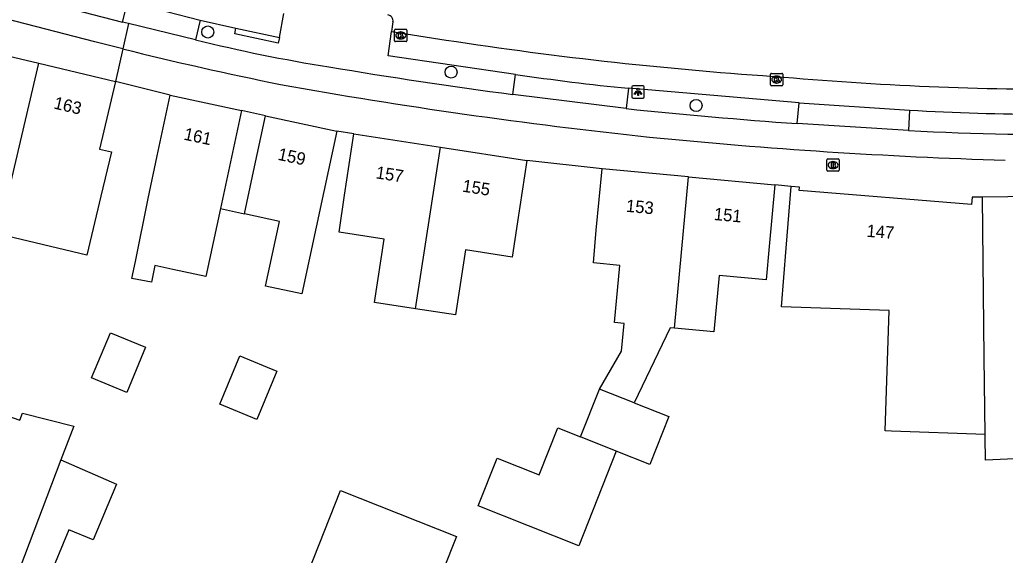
# Model space of a CAD drawing. Extents: x 158087 to 159494, y 382905 to 383981.
# Drawn here: x 158597.5 to 158677.2, y 383097.9 to 383141.2 of the extents above; entities that cross this region are included whole.
import ezdxf

# ---------------------------------------------------------------- set-up
doc = ezdxf.new("R2010")
doc.units = 0
for name, color, linetype in [('IMGEO_Boom', 7, 'Continuous'), ('IMGEO_Brandkraan', 7, 'Continuous'), ('IMGEO_Fietspad_gesloten', 7, 'Continuous'), ('IMGEO_Kolk', 7, 'Continuous'), ('IMGEO_Lichtpunt', 7, 'Continuous'), ('IMGEO_Pand', 7, 'Continuous'), ('IMGEO_Pand_nummerreeks', 7, 'Continuous'), ('IMGEO_Pand_overbouw', 7, 'Continuous'), ('IMGEO_Parkeervlak_open', 7, 'Continuous'), ('IMGEO_Rijbaan_lokaal_gesloten', 7, 'Continuous'), ('IMGEO_Voetpad_open', 7, 'Continuous')]:
    doc.layers.add(name, color=color, linetype=linetype)

msp = doc.modelspace()

# ---------------------------------------------------------------- linework, layer by layer
at = {"layer": 'IMGEO_Boom'}
for centre in [(158612.695, 383140.229), (158632.365, 383136.991), (158652.17, 383134.289)]:
    msp.add_circle(centre, 0.489, dxfattribs=at)
at = {"layer": 'IMGEO_Brandkraan'}
for p, q in [((158662.74, 383129.05), (158662.74, 383129.902)), ((158662.815, 383129.976), (158663.667, 383129.976)), ((158663.741, 383129.902), (158663.741, 383129.05)), ((158663.251, 383129.196), (158663.226, 383129.196)), ((158663.228, 383129.756), (158663.253, 383129.756)), ((158663.667, 383128.976), (158662.815, 383128.976))]:
    msp.add_line(p, q, dxfattribs=at)
for points in [[(158662.74, 383129.05), (158662.74, 383129.902)], [(158662.815, 383129.976), (158663.667, 383129.976)], [(158663.741, 383129.902), (158663.741, 383129.05)], [(158663.088, 383129.676), (158663.088, 383129.276), (158663.301, 383129.276)], [(158663.319, 383129.676), (158663.088, 383129.676)], [(158663.267, 383129.595), (158663.213, 383129.595), (158663.213, 383129.519)], [(158663.213, 383129.519), (158663.266, 383129.519)], [(158663.275, 383129.443), (158663.213, 383129.443), (158663.213, 383129.362)], [(158663.213, 383129.362), (158663.275, 383129.362)], [(158663.667, 383128.976), (158662.815, 383128.976)]]:
    msp.add_lwpolyline(points, dxfattribs=at)
for centre, radius, start, end in [((158662.817, 383129.9), 0.0765, 91.55205, 178.44795), ((158662.817, 383129.9), 0.0765, 91.55205, 178.44795), ((158663.665, 383129.9), 0.0765, 1.55205, 88.44795), ((158663.665, 383129.9), 0.0765, 1.55205, 88.44795), ((158662.817, 383129.052), 0.0765, 181.55205, 268.44795), ((158662.817, 383129.052), 0.0765, 181.55205, 268.44795), ((158663.268, 383129.557), 0.0379, 267.82845, 90.93552), ((158663.276, 383129.402), 0.0404, 269.87594, 90.50774), ((158663.307, 383129.527), 0.251, 268.66757, 293.53466), ((158663.323, 383129.531), 0.145, 59.4692, 91.53667), ((158663.348, 383129.578), 0.0922, 285.51372, 58.15012), ((158663.353, 383129.386), 0.105, 301.31148, 78.98903), ((158663.665, 383129.052), 0.0765, 271.55205, 358.44795), ((158663.665, 383129.052), 0.0765, 271.55205, 358.44795)]:
    msp.add_arc(centre, radius, start, end, dxfattribs=at)
for centre, major_axis, ratio, start_param, end_param in [((158663.227, 383129.476), (-0.387, 0.002), 0.722429, 4.712389, 7.853982), ((158663.252, 383129.476), (-0.39, 0.002), 0.717154, 1.570796, 4.712389)]:
    msp.add_ellipse(centre, major_axis=major_axis, ratio=ratio, start_param=start_param, end_param=end_param, dxfattribs=at)
at = {"layer": 'IMGEO_Fietspad_gesloten'}
for points in [[(158605.821, 383138.869), (158603.579, 383139.437), (158566.233, 383149.116), (158551.161, 383152.802)], [(158595.342, 383143.755), (158605.812, 383141.029)], [(158606.277, 383140.917), (158605.812, 383141.029)], [(158606.277, 383140.917), (158605.821, 383138.869)], [(158611.717, 383139.601), (158606.277, 383140.917)], [(158646.524, 383134.037), (158637.361, 383135.18)], [(158669.341, 383132.266), (158660.347, 383132.823)]]:
    msp.add_lwpolyline(points, dxfattribs=at)
for centre, radius, start, end in [((158641.65, 383259.404), 123.486, 255.97176, 261.07303), ((158678.323, 383430.181), 300.199, 256.02409, 258.52003), ((158692.906, 383555.601), 424.074, 260.44169, 262.4738), ((158692.742, 383549.43), 420.041, 259.83006, 263.94093), ((158692.294, 383575.88), 444.207, 264.08595, 265.87584), ((158681.389, 383358.442), 226.496, 266.95077, 275.08287), ((158689.949, 383550.143), 420.466, 264.32963, 268.25752)]:
    msp.add_arc(centre, radius, start, end, dxfattribs=at)
at = {"layer": 'IMGEO_Kolk'}
for p, q in [((158627.795, 383139.527), (158627.795, 383140.379)), ((158627.87, 383140.453), (158628.722, 383140.453)), ((158628.283, 383140.233), (158628.308, 383140.233)), ((158628.796, 383140.379), (158628.796, 383139.527)), ((158628.722, 383139.453), (158627.87, 383139.453)), ((158628.306, 383139.673), (158628.281, 383139.673)), ((158658.183, 383135.961), (158658.183, 383136.813)), ((158658.258, 383136.887), (158659.11, 383136.887)), ((158658.671, 383136.667), (158658.696, 383136.667)), ((158659.184, 383136.813), (158659.184, 383135.961)), ((158659.11, 383135.887), (158658.258, 383135.887)), ((158658.694, 383136.107), (158658.669, 383136.107))]:
    msp.add_line(p, q, dxfattribs=at)
for points in [[(158627.795, 383139.527), (158627.795, 383140.379)], [(158627.87, 383140.453), (158628.722, 383140.453)], [(158628.796, 383140.379), (158628.796, 383139.527)], [(158628.722, 383139.453), (158627.87, 383139.453)], [(158628.116, 383140.153), (158628.239, 383140.153), (158628.239, 383140.002), (158628.369, 383140.153), (158628.533, 383140.153), (158628.387, 383140.002), (158628.54, 383139.753), (158628.388, 383139.753), (158628.303, 383139.917), (158628.239, 383139.85), (158628.239, 383139.753), (158628.116, 383139.753), (158628.116, 383140.153)], [(158658.183, 383135.961), (158658.183, 383136.813)], [(158658.258, 383136.887), (158659.11, 383136.887)], [(158658.504, 383136.587), (158658.627, 383136.587), (158658.627, 383136.436), (158658.757, 383136.587), (158658.921, 383136.587), (158658.775, 383136.436), (158658.928, 383136.187), (158658.776, 383136.187), (158658.691, 383136.351), (158658.627, 383136.284), (158658.627, 383136.187), (158658.504, 383136.187), (158658.504, 383136.587)], [(158659.184, 383136.813), (158659.184, 383135.961)], [(158659.11, 383135.887), (158658.258, 383135.887)]]:
    msp.add_lwpolyline(points, dxfattribs=at)
for centre, start, end in [((158627.872, 383140.377), 91.55205, 178.44795), ((158627.872, 383140.377), 91.55205, 178.44795), ((158628.72, 383140.377), 1.55205, 88.44795), ((158628.72, 383140.377), 1.55205, 88.44795), ((158627.872, 383139.529), 181.55205, 268.44795), ((158627.872, 383139.529), 181.55205, 268.44795), ((158628.72, 383139.529), 271.55205, 358.44795), ((158628.72, 383139.529), 271.55205, 358.44795), ((158658.26, 383136.811), 91.55205, 178.44795), ((158658.26, 383136.811), 91.55205, 178.44795), ((158659.108, 383136.811), 1.55205, 88.44795), ((158659.108, 383136.811), 1.55205, 88.44795), ((158658.26, 383135.963), 181.55205, 268.44795), ((158658.26, 383135.963), 181.55205, 268.44795), ((158659.108, 383135.963), 271.55205, 358.44795), ((158659.108, 383135.963), 271.55205, 358.44795)]:
    msp.add_arc(centre, 0.0765, start, end, dxfattribs=at)
for centre, major_axis, ratio, start_param, end_param in [((158628.282, 383139.953), (-0.387, 0.002), 0.722429, 4.712389, 7.853982), ((158628.307, 383139.953), (-0.39, 0.002), 0.717154, 1.570796, 4.712389), ((158658.67, 383136.387), (-0.387, 0.002), 0.722429, 4.712389, 7.853982), ((158658.695, 383136.387), (-0.39, 0.002), 0.717154, 1.570796, 4.712389)]:
    msp.add_ellipse(centre, major_axis=major_axis, ratio=ratio, start_param=start_param, end_param=end_param, dxfattribs=at)
at = {"layer": 'IMGEO_Lichtpunt'}
for p, q in [((158646.98, 383135.793), (158646.98, 383134.986)), ((158646.98, 383135.793), (158646.98, 383134.986)), ((158647.882, 383135.888), (158647.074, 383135.888)), ((158647.882, 383135.888), (158647.074, 383135.888)), ((158647.976, 383134.986), (158647.976, 383135.793)), ((158647.976, 383134.986), (158647.976, 383135.793)), ((158647.074, 383134.892), (158647.882, 383134.892)), ((158647.074, 383134.892), (158647.882, 383134.892))]:
    msp.add_line(p, q, dxfattribs=at)
for points in [[(158647.354, 383135.457), (158647.393, 383135.429), (158647.205, 383135.167), (158647.167, 383135.194), (158647.354, 383135.457)], [(158647.456, 383135.409), (158647.503, 383135.409), (158647.503, 383135.087), (158647.456, 383135.087), (158647.456, 383135.409)], [(158647.566, 383135.429), (158647.604, 383135.456), (158647.791, 383135.194), (158647.752, 383135.166), (158647.566, 383135.429)]]:
    msp.add_lwpolyline(points, dxfattribs=at)
msp.add_circle((158647.479, 383135.591), 0.0994, dxfattribs=at)
for centre, start, end in [((158647.074, 383135.793), 90, 180), ((158647.074, 383135.793), 90, 180), ((158647.882, 383135.793), 0, 90), ((158647.882, 383135.793), 0, 90), ((158647.074, 383134.986), 180, 270), ((158647.074, 383134.986), 180, 270), ((158647.882, 383134.986), 270, 0), ((158647.882, 383134.986), 270, 360)]:
    msp.add_arc(centre, 0.0946, start, end, dxfattribs=at)
at = {"layer": 'IMGEO_Pand'}
for points in [[(158593.093, 383139.116), (158599.052, 383137.699)], [(158595.769, 383123.894), (158599.052, 383137.699)], [(158599.052, 383137.699), (158605.232, 383136.229)], [(158605.232, 383136.229), (158603.934, 383130.772), (158604.907, 383130.541), (158604.053, 383126.952), (158602.927, 383122.188), (158595.769, 383123.894)], [(158615.417, 383133.88), (158614.368, 383128.992), (158613.716, 383125.951), (158612.539, 383120.466), (158609.867, 383121.039), (158608.412, 383121.351), (158608.14, 383120.001), (158606.571, 383120.316), (158606.847, 383121.687), (158607.869, 383126.766), (158608.612, 383130.227), (158609.661, 383135.115)], [(158609.661, 383135.115), (158615.417, 383133.88)], [(158623.132, 383132.225), (158622.084, 383127.337), (158620.306, 383119.052), (158617.371, 383119.682), (158618.496, 383124.925), (158615.667, 383125.532), (158616.32, 383128.574), (158617.368, 383133.462)], [(158617.368, 383133.462), (158623.132, 383132.225)], [(158629.495, 383117.864), (158626.162, 383118.377), (158626.948, 383123.478), (158623.319, 383124.04), (158623.747, 383127.051), (158624.508, 383131.992)], [(158624.508, 383131.992), (158631.505, 383130.914)], [(158629.495, 383117.864), (158631.505, 383130.914)], [(158631.505, 383130.914), (158638.5, 383129.837)], [(158638.5, 383129.837), (158637.739, 383124.896), (158637.303, 383122.04), (158633.521, 383122.617), (158632.712, 383117.368), (158629.495, 383117.864)], [(158644.365, 383111.369), (158646.14, 383114.437), (158646.349, 383116.663), (158645.577, 383116.736), (158646.011, 383121.356), (158643.877, 383121.574), (158644.101, 383124.199), (158644.568, 383129.177)], [(158651.56, 383128.52), (158644.568, 383129.177)], [(158650.413, 383116.281), (158651.56, 383128.52)], [(158651.56, 383128.52), (158658.548, 383127.864)], [(158658.548, 383127.864), (158658.08, 383122.886), (158657.842, 383120.185), (158654.037, 383120.534), (158653.609, 383115.981), (158650.413, 383116.281)], [(158675.54, 383107.693), (158667.965, 383107.961), (158667.444, 383107.981), (158667.79, 383117.715), (158659.07, 383118.025), (158659.449, 383122.765), (158659.849, 383127.748)], [(158675.324, 383126.884), (158674.489, 383126.873), (158674.441, 383126.287), (158660.496, 383127.406), (158660.52, 383127.695), (158659.849, 383127.748)], [(158691.677, 383127.093), (158675.324, 383126.884)], [(158675.54, 383107.693), (158675.47, 383113.918), (158675.324, 383126.884)], [(158650.413, 383116.281), (158650.079, 383116.312), (158647.167, 383110.256)], [(158606.142, 383111.091), (158603.31, 383112.263), (158604.822, 383115.916), (158607.654, 383114.743), (158606.142, 383111.091)], [(158616.661, 383108.909), (158613.671, 383110.147), (158615.292, 383114.063), (158618.282, 383112.825), (158616.661, 383108.909)], [(158590.961, 383111.176), (158595.246, 383110.044), (158595.115, 383109.687), (158597.5, 383108.865), (158597.722, 383109.415), (158601.861, 383108.361), (158600.828, 383105.639)], [(158642.83, 383107.505), (158644.365, 383111.369)], [(158647.167, 383110.256), (158644.365, 383111.369)], [(158647.167, 383110.256), (158649.969, 383109.143), (158648.434, 383105.279), (158645.72, 383106.357)], [(158645.72, 383106.357), (158642.679, 383098.702), (158634.552, 383101.931), (158636.084, 383105.789), (158639.474, 383104.443), (158640.982, 383108.239), (158642.83, 383107.505)], [(158679.738, 383105.803), (158675.563, 383105.615), (158675.542, 383107.491), (158675.54, 383107.693)], [(158645.72, 383106.357), (158642.83, 383107.505)], [(158600.828, 383105.639), (158605.331, 383103.673), (158603.426, 383099.185), (158601.461, 383099.98), (158599.757, 383095.899), (158597.507, 383096.888)], [(158600.828, 383105.639), (158597.507, 383096.888)], [(158619.964, 383094.426), (158623.437, 383103.168), (158632.811, 383099.445), (158629.501, 383091.11)]]:
    msp.add_lwpolyline(points, dxfattribs=at)
at = {"layer": 'IMGEO_Pand_overbouw'}
msp.add_lwpolyline([(158617.368, 383133.462), (158615.417, 383133.88), (158614.368, 383128.992), (158613.716, 383125.951), (158615.667, 383125.532), (158616.32, 383128.574)], close=True, dxfattribs=at)
at = {"layer": 'IMGEO_Parkeervlak_open'}
for points in [[(158612.09, 383141.195), (158614.978, 383140.539)], [(158618.5, 383139.782), (158618.856, 383141.718)], [(158637.57, 383136.806), (158627.271, 383138.3), (158627.539, 383140.278)], [(158660.507, 383134.495), (158646.695, 383135.677)]]:
    msp.add_lwpolyline(points, dxfattribs=at)
msp.add_arc((158681.594, 383344.599), 211.032, 266.69024, 272.69845, dxfattribs=at)
at = {"layer": 'IMGEO_Rijbaan_lokaal_gesloten'}
for points in [[(158627.667, 383141.046), (158627.539, 383140.278)], [(158627.539, 383140.278), (158631.966, 383139.58)]]:
    msp.add_lwpolyline(points, dxfattribs=at)
for centre, radius, start, end in [((158627.187, 383141.129), 0.487, 350.15016, 83.03793), ((158680.506, 383456.049), 320.17, 261.2799, 266.19726), ((158682.233, 383401.778), 266.187, 265.05149, 270.44914)]:
    msp.add_arc(centre, radius, start, end, dxfattribs=at)
at = {"layer": 'IMGEO_Voetpad_open'}
for points in [[(158605.812, 383141.029), (158606.226, 383142.683)], [(158606.226, 383142.683), (158606.647, 383142.576), (158612.09, 383141.195)], [(158612.09, 383141.195), (158611.717, 383139.601)], [(158618.5, 383139.782), (158618.377, 383139.33), (158614.876, 383140.088), (158614.978, 383140.539)], [(158614.978, 383140.539), (158618.5, 383139.782)], [(158605.821, 383138.869), (158605.232, 383136.229)], [(158609.661, 383135.115), (158605.232, 383136.229)], [(158637.361, 383135.18), (158637.57, 383136.806)], [(158646.695, 383135.677), (158646.524, 383134.037)], [(158617.368, 383133.462), (158615.417, 383133.88)], [(158660.347, 383132.823), (158660.507, 383134.495)], [(158660.507, 383134.495), (158669.41, 383133.919)], [(158669.41, 383133.919), (158669.341, 383132.266)], [(158624.508, 383131.992), (158623.132, 383132.225)], [(158644.568, 383129.177), (158638.5, 383129.837)], [(158659.849, 383127.748), (158658.548, 383127.864)]]:
    msp.add_lwpolyline(points, dxfattribs=at)
msp.add_arc((158664.896, 383320.227), 185.445, 261.52633, 264.3674, dxfattribs=at)

# ---------------------------------------------------------------- texts
at = {"layer": 'IMGEO_Pand_nummerreeks'}
for s, rotation, p in [('163', 346.62197, (158600.185, 383134.057)), ('161', 347.89029, (158610.704, 383131.537)), ('159', 347.88759, (158618.302, 383129.907)), ('157', 351.2443, (158626.235, 383128.407)), ('155', 351.2443, (158633.231, 383127.33)), ('153', 354.63712, (158646.475, 383125.703)), ('151', 354.63452, (158653.578, 383125.037)), ('147', 355.41061, (158665.923, 383123.68))]:
    msp.add_text(s, height=1, rotation=rotation, dxfattribs=at).set_placement(p)

doc.saveas('drawing.dxf')
